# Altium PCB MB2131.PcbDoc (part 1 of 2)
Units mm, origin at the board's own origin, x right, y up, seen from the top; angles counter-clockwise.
Board outline 22 x 56 mm, 2 copper layers (Top Layer, Bottom Layer), stack 0.87 mm thick; 89 components, 71 nets, 391 pads, 308 vias.
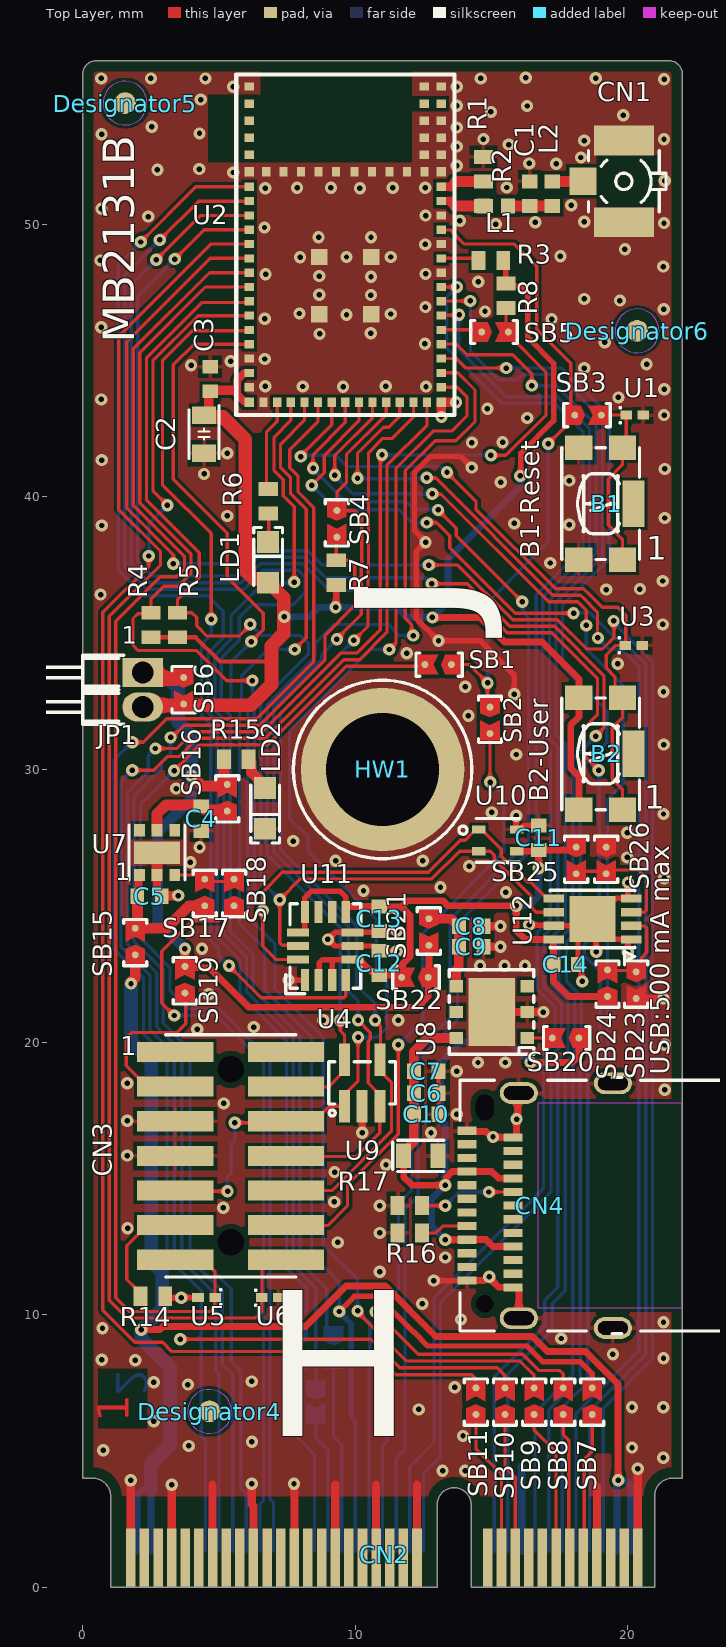
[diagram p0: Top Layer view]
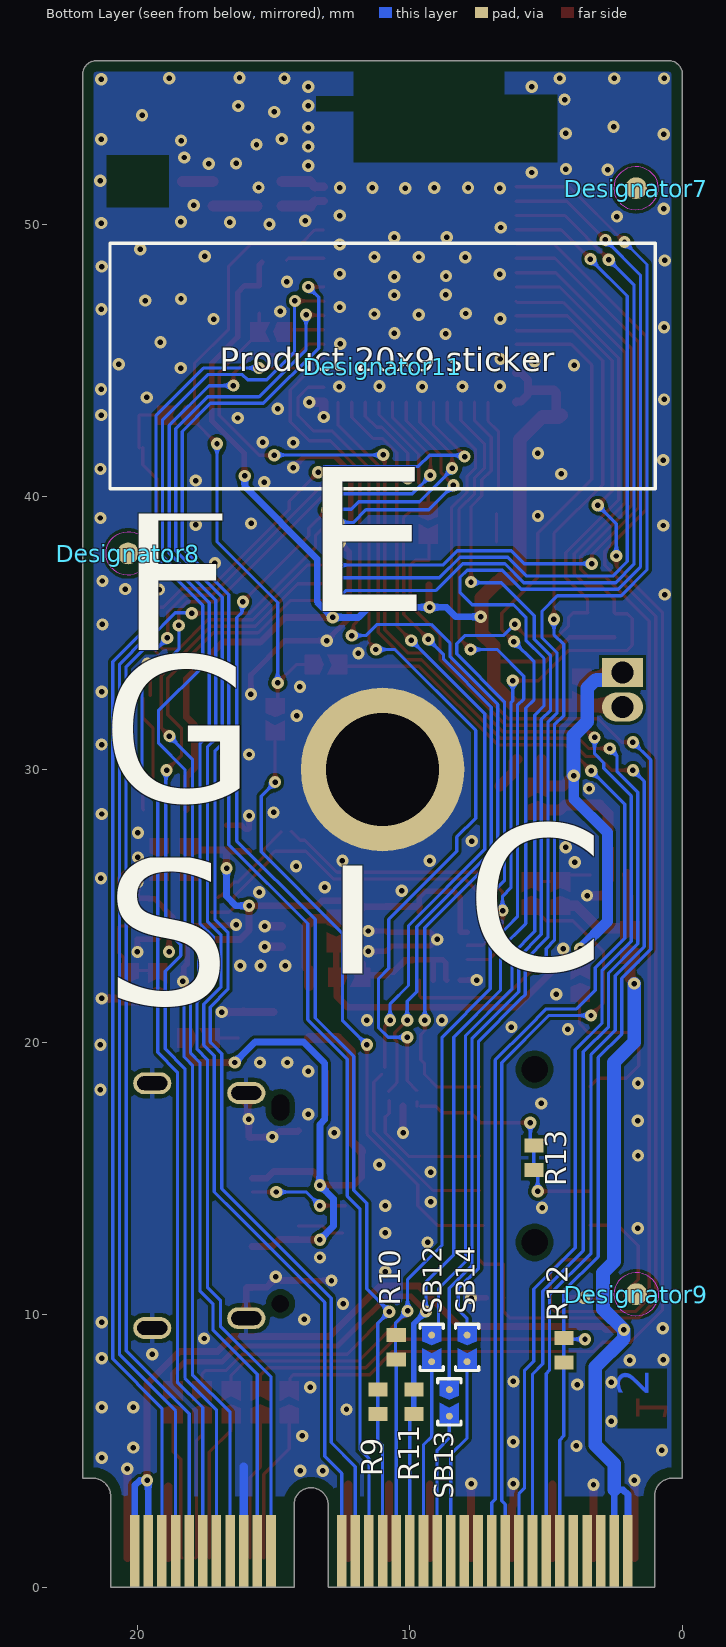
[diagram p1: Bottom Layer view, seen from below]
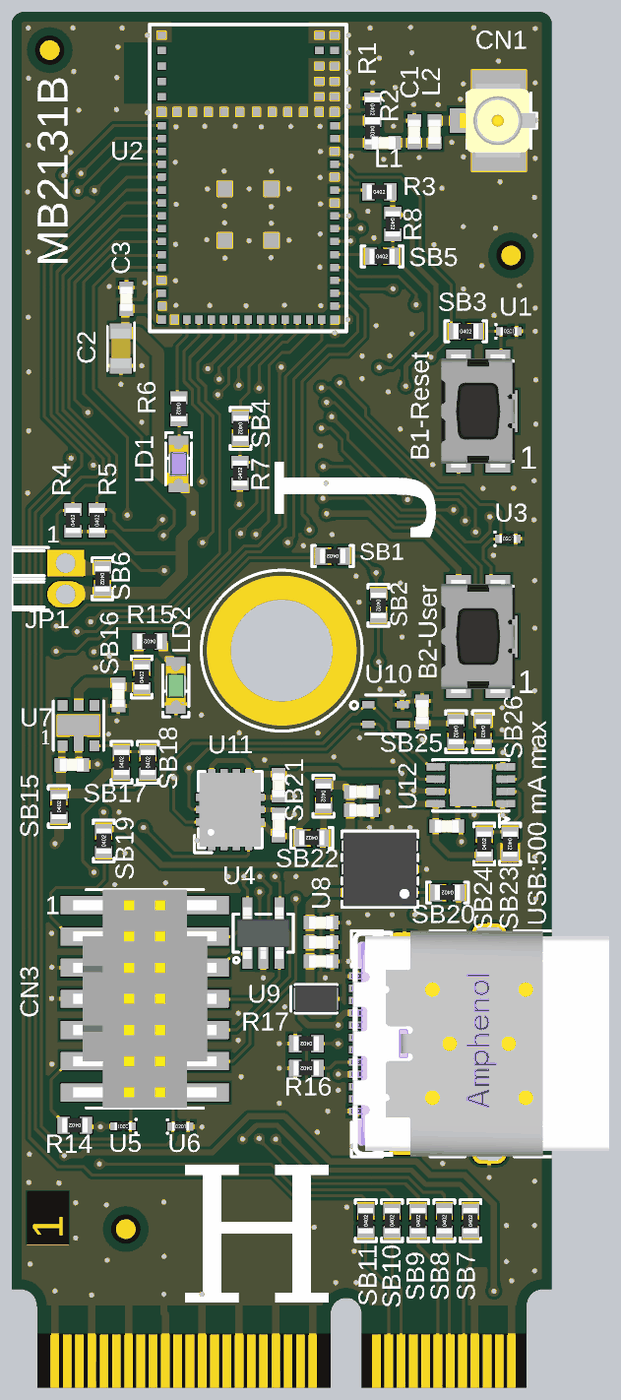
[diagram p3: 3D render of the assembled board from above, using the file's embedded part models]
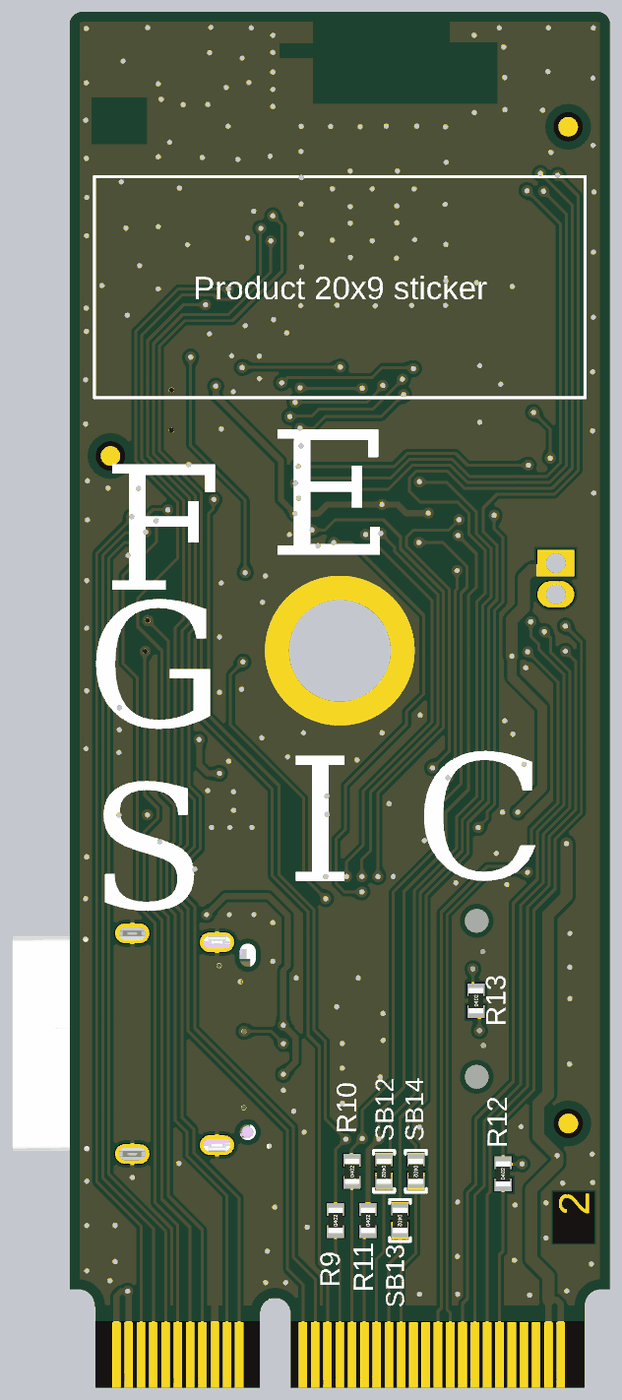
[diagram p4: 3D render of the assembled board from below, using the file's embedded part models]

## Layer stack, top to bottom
Top Solder: solder mask 0.015, Solder Resist, Dk 3.5
Top Layer: signal copper 0.035
Dielectric 1: core 0.8, FR-4, Dk 4.8
Bottom Layer: signal copper 0.035
Bottom Solder: solder mask 0.015, Solder Resist, Dk 3.5

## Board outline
1.025,0 1.025,3.337 ccw(c0.362,3.337) 0.362,4 0,4 0,55.5 cw(c0.5,55.5) 0.5,56 21.5,56 cw(c21.5,55.5) 22,55.5 22,4 21.638,4 ccw(c21.638,3.337) 20.975,3.337 20.975,0 14.25,0 14.25,3.025 ccw(c13.625,3.025) 13.625,3.65 ccw(c13.625,3.025) 13,3.025 13,0

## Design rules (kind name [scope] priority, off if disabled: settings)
BoardOutlineClearance [All] p1: gap=0.4 ignorepadtopadclearanceinfootprint=FALSE
Clearance [All] p1: gap=0.12 ignorepadtopadclearanceinfootprint=TRUE except(0: THPad-Hole; 0.15: Via-Text Fill-Fill Fill-Poly Fill-Region Fill-Text Poly-Poly Poly-Region Poly-Text Region-Region Region-Text Text-Text; 0.2: Track-Hole SMDPad-SMDPad SMDPad-THPad SMDPad-Text SMDPad-Hole THPad-THPad THPad-Text Poly-Hole; 0.3: Arc-Hole Via-Hole Fill-Hole Region-Hole Text-Hole)
ComponentClearance [All] p1: gap=0.1 collisioncheckmode=3 verticalgap=0 showdistances=FALSE
HoleSize [All] p1: absolutevalues=TRUE maxlimit=10 minlimit=0.025 maxpercent=80.000 minpercent=20.000
MinimumSolderMaskSliver [All] p1: minsoldermaskwidth=0.1
PlaneConnect [All] p1: planeconnectstyle=Relief reliefexpansion=0.508 reliefentries=4 reliefconductorwidth=0.21 reliefairgap=0.21
PolygonConnect PolygonConnect_via [IsVia] p1: connectstyle=Direct reliefconductorwidth=0.254 reliefentries=4 polygonreliefangle="90 Angle" airgapwidth=0.254
PolygonConnect [All] p2: connectstyle=Relief reliefconductorwidth=0.15 reliefentries=4 polygonreliefangle="90 Angle" airgapwidth=0.15
RoutingVias [All] p1: holewidth=0.3 width=0.55 viastyle="Through Hole" minholewidth=0.3 minwidth=0.55 maxholewidth=0.3 maxwidth=0.55 useviatemplates=TRUE viatemplateguid#1={F3ABD56A-64D8-4EC3-B00D-3E2DD87A5A49} viatemplatename#1=v45h20m0mx0
SilkToSilkClearance [All] p1: silktosilkclearance=0.2
SilkToSolderMaskClearance [IsPad] p1: minsilkscreentomaskgap=0.2 clearancetoexposedcopper=TRUE
SolderMaskExpansion [All] p1: expansion=0.102 istentingtop=FALSE
Width Width_RF [InNetClass('RF')] p1: maxlimit=1.3 minlimit=0.4 preferedwidth=1.3 toplayer_maxwidth=0.4 toplayer_prefwidth=0.4 impedanceprofiledriven=TRUE impedanceprofileid={58A662D9-11D8-47AE-92A8-C80169B12F76} impedanceprofilevalue=50.000000 minimp=50.000000 maximp=50.000000 favimp=50.000000
Width Width_Alim [InNetClass('Alim')] p2: maxlimit=0.5 minlimit=0.2 preferedwidth=0.25 minimp=50.000000 maximp=50.000000 favimp=50.000000
Width [All] p3: maxlimit=0.5 minlimit=0.12 preferedwidth=0.12 minimp=50.000000 maximp=50.000000 favimp=50.000000
24 further rules are at their usual default settings.

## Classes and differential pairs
net class RF: ANT ANTIN ANTOUT NetC1_2
component class U_Mems: C11 C12 C13 C14 SB22 SB23 SB24 SB25 SB26 U10 U11 U12
component class U_MCU: B1 B2 C1 C2 C3 CN1 JP1 L1 L2 LD1 R1 R2 R3 R4 R5 R6 R7 R8 SB1 SB2 SB3 SB4 SB5 SB6 U1 U2 U3
component class U_M2: CN2 HW1 R9 R10 R11 R12 SB7 SB8 SB9 SB10 SB11 SB12 SB13 SB14
component class U_External_Debug_Interface: CN3 R13 R14 U4 U5 U6
component class U_Board_Power: C4 C5 C6 C7 C8 C9 C10 CN4 LD2 R15 R16 R17 SB15 SB16 SB17 SB18 SB19 SB20 SB21 U7 U8 U9

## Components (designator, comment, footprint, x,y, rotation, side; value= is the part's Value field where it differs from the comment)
B1 "SW-PUSH-CMS_KMR2_BLACK" SWI_C&K_Y78B23110FP__ITT_KMR231GLFS 19,39.75 r270 top value=KMR231GLFS
B2 "SW-PUSH-CMS_KMR2_BLACK" SWI_C&K_Y78B23110FP__ITT_KMR231GLFS 19,30.575 r270 top value=KMR231GLFS
C1 "Capacitor" C0402 16.4,51.125 r270 top value=22pF
C2 "Capacitor" C0603 4.45,42.3 r90 top value=4.7uF
C3 "Capacitor" C0402 4.675,44.325 r270 top value=100nF
C4 "Capacitor" C0402 4.35,28.2 r90 top value=100nF
C5 "Capacitor" C0402 2.45,25.35 r180 top value=1uF
C6 "Capacitor" C0402 12.6,18.125 r180 top value=1uF
C7 "Capacitor" C0402 12.6,18.925 r180 top value=100nF
C8 "Capacitor" C0402 14.25,24.25 r180 top value=1uF
C9 "Capacitor" C0402 14.25,23.5 r180 top value=100nF
C10 "Capacitor" C0402 12.6,17.35 r180 top value=100pF
C11 "Capacitor" C0402 16.725,27.5 r270 top value=100nF
C12 "Capacitor" C0402 10.875,22.9 r270 top value=100nF
C13 "Capacitor" C0402 10.875,24.525 r90 top value=100nF
C14 "Capacitor" C0402 17.725,22.85 r180 top value=100nF
CARTOUCH-1 "Comment" Sheetbox_2L2S -32.492,-33.227 r0 top
CN1 "U.FL-R-SMT-1" CON_HRS_U.FL-R-SMT-1 19.85,51.575 r270 top value=Con_RF_U.FL-R-SMT-1
CN2 "M2_MALE-CONNECTOR_KEY-E_3V3" CON_BOARD_GOLDFINGER_PCI_EXPRESS_X75_M2_KEY-E 11,0 r0 top value=M.2_KeyE_Male
CN3 "Header 7x2" CON_STDC14_Receiver_SMALL 5.425,15.825 r270 top
CN4 "USB_TYPE_C_Receptacle" CON_USB-TYPEC_AMPHENOL_12401826E412A 14.75,14 r90 top value=USB_C_12401826E412A
Designator4 "Comment" MIRE_PLACE_SMD_0P8MM 4.65,6.45 r0 top
Designator5 "Comment" MIRE_PLACE_SMD_0P8MM 1.552,54.446 r0 top
Designator6 "Comment" MIRE_PLACE_SMD_0P8MM 20.339,46.091 r0 top
Designator7 "Comment" MIRE_PLACE_SMD_0P8MM 1.7,51.325 r180 bottom
Designator8 "Comment" MIRE_PLACE_SMD_0P8MM 20.339,37.926 r180 bottom
Designator9 "Comment" MIRE_PLACE_SMD_0P8MM 1.692,10.751 r180 bottom
Designator11 "Comment" STICKER_PRODUCT_20X9 11,44.8 r180 bottom
HW1 "M2_POSITION_HOLE" MISC_REGO_S001_00001_A42_R 11,30 r0 top value=S001-00001-A42-R
JP1 "Jumper_Header1.27 2x1 Fitted" CON_WP_707-2-02-2-20-00 2.2,32.925 r270 top value="Header 2x1"
L1 "Inductor" C0402 15.15,50.675 r0 top value=3.3nH
L2 "Inductor" C0402 17.225,51.125 r90 top value=3.3nH
LD1 "LED_blue" LED_0603_OSRAM_LB-Q39G-L2OO-35-1_BLUE_1A2K_H0P4 6.8,37.6 r90 top value=Blue
LD2 "LED_green" LED_0603_OSRAM_LG-Q396-PS-35_GREEN_1A2K_H0P4 6.69,28.575 r270 top value=Green
R1 "Resistor" R0402 14.7,52.025 r270 top value=0R
R2 "Resistor" R0402 14.7,51.125 r270 top value=0R
R3 "Resistor" R0402 14.975,48.675 r0 top value=10K
R4 "Resistor" R0402 2.5,35.3 r90 top value=3K3
R5 "Resistor" R0402 3.475,35.3 r90 top value=3K3
R6 "Resistor" R0402 6.804,39.844 r270 top value=150R
R7 "Resistor" R0402 9.3,37.225 r90 top value=3K3
R8 "Resistor" R0402 15.525,47.375 r270 top value=3K3
R9 "Resistor" R0402 11.175,6.8 r90 bottom value=0R
R10 "Resistor" R0402 10.5,8.8 r90 bottom value=0R
R11 "Resistor" R0402 9.85,6.8 r90 bottom value=0R
R12 "Resistor" R0402 4.35,8.7 r90 bottom value=0R
R13 "Resistor" R0402 5.45,15.75 r90 bottom value=0R
R14 "Resistor" R0402 2.575,10.675 r180 top value=100R
R15 "Resistor" R0402 5.625,30.375 r180 top value=620R
R16 "Resistor" R0402 12,13 r180 top value=5K1
R17 "Resistor" R0402 12,14 r180 top value=5K1
SB1 "SB_ON" SOLDER-BRIDGE_R0402-0R 13.075,33.85 r180 top value=0R
SB2 "SB_ON" SOLDER-BRIDGE_R0402-0R 14.94,31.84 r270 top value=0R
SB3 "SB_ON" SOLDER-BRIDGE_R0402-0R 18.5,43 r0 top value=0R
SB4 "SB_ON" SOLDER-BRIDGE_R0402-0R 9.325,39.05 r270 top value=0R
SB5 "SB_ON" SOLDER-BRIDGE_R0402-0R 15.088,46.05 r0 top value=0R
SB6 "SB_ON" SOLDER-BRIDGE_R0402-0R 3.7,32.925 r270 top value=0R
SB7 "SB_ON" SOLDER-BRIDGE_R0402-0R 18.69,6.789 r90 top value=0R
SB8 "SB_ON" SOLDER-BRIDGE_R0402-0R 17.624,6.789 r90 top value=0R
SB9 "SB_ON" SOLDER-BRIDGE_R0402-0R 16.558,6.789 r90 top value=0R
SB10 "SB_ON" SOLDER-BRIDGE_R0402-0R 15.491,6.789 r90 top value=0R
SB11 "SB_ON" SOLDER-BRIDGE_R0402-0R 14.425,6.789 r90 top value=0R
SB12 "SB_ON" SOLDER-BRIDGE_R0402-0R 9.2,8.8 r270 bottom value=0R
SB13 "SB_ON" SOLDER-BRIDGE_R0402-0R 8.55,6.8 r270 bottom value=0R
SB14 "SB_ON" SOLDER-BRIDGE_R0402-0R 7.9,8.8 r270 bottom value=0R
SB15 "SB_ON" SOLDER-BRIDGE_R0402-0R 1.925,23.65 r90 top value=0R
SB16 "SB_ON" SOLDER-BRIDGE_R0402-0R 5.3,28.925 r90 top value=0R
SB17 "SB_ON" SOLDER-BRIDGE_R0402-0R 4.475,25.45 r90 top value=0R
SB18 "SB_ON" SOLDER-BRIDGE_R0402-0R 5.55,25.45 r90 top value=0R
SB19 "SB_ON" SOLDER-BRIDGE_R0402-0R 3.75,22.25 r90 top value=0R
SB20 "SB_ON" SOLDER-BRIDGE_R0402-0R 17.75,20.15 r180 top value=0R
SB21 "SB_ON" SOLDER-BRIDGE_R0402-0R 12.7,24.075 r270 top value=0R
SB22 "SB_ON" SOLDER-BRIDGE_R0402-0R 12.225,22.375 r180 top value=0R
SB23 "SB_ON" SOLDER-BRIDGE_R0402-0R 20.3,22.125 r270 top value=0R
SB24 "SB_ON" SOLDER-BRIDGE_R0402-0R 19.25,22.125 r90 top value=0R
SB25 "SB_ON" SOLDER-BRIDGE_R0402-0R 18.1,26.7 r270 top value=0R
SB26 "SB_ON" SOLDER-BRIDGE_R0402-0R 19.2,26.7 r270 top value=0R
U1 "ESD-TRANSIL" ESD_ST0201 20.25,43 r0 top value=ESDALC6V1-1U2
U2 "STM32WBA5M" MOD_STM_76P_8X12P5_H1P37 9.633,49.247 r0 top value=STM32WBA5MMGH6
U3 "ESD-TRANSIL" ESD_ST0201 20.212,34.55 r0 top value=ESDALC6V1-1U2
U4 "ESDALC6V1W5" ESD_SOT323-5L 10.25,18.5 r0 top
U5 "ESD-TRANSIL" ESD_ST0201 4.541,10.638 r180 top value=ESDALC6V1-1U2
U6 "ESD-TRANSIL" ESD_ST0201 6.875,10.625 r0 top value=ESDALC6V1-1U2
U7 "AP22814ASN-7" ICC_DFN2020-6-EPAD_2X2_P065 2.725,26.95 r0 top
U8 "LD39050PU33R" ICC_DFN6-EPAD_3X3_P095 15,21.1 r90 top
U9 "ESD-TRANSIL" ESD_QFN1610_2N_1K_2A 12.4,15.825 r0 top value=ESDA25P35-1U1M
U10 "SHT4X" ICC_SENSOR_SHT40-AD1B-R2_DFN4-EPAD_1P5X1P5_P050 15.225,27.4 r0 top value=SHT40-AD1B-R2
U11 "ISM330DHCX" ICC_LGA14_3X2P5_P050 8.9,23.525 r90 top value=ISM330DHCXTR
U12 "M24128-DFMC6TP" ICC_DFN8-EPAD_2X3_P050 18.7,24.515 r270 top value=M24256-DFMC6TG

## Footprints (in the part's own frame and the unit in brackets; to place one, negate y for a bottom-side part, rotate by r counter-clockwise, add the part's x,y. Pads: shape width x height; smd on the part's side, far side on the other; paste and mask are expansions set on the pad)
C0402 [mm]
  rect 0.51x0.56 smd mask+0.05: 1(-0.45,0) 2(0.45,0)
  body extent -0.5,-0.3 0.5,0.3, height 0.4
C0603 [mm]
  rect 0.64x0.89 smd mask+0.05: 1(-0.7,0) 2(0.7,0)
  silkscreen extent -0.9,-0.55 1.05,0.55, body extent -0.9,-0.5 0.9,0.5, height 1.4
CON_BOARD_GOLDFINGER_PCI_EXPRESS_X75_M2_KEY-E [mm] "MCD-03876"
  rect 0.35x2.15 smd paste-1 mask+0.05: 1(9.362,1.075) 3(8.862,1.075) 5(8.362,1.075) 7(7.862,1.075) 9(7.362,1.075) 11(6.863,1.075) 13(6.363,1.075) 15(5.863,1.075) 17(5.363,1.075) 19(4.863,1.075) 21(4.363,1.075) 23(3.863,1.075) 33(1.262,1.075) 35(0.763,1.075) 37(0.263,1.075) 39(-0.237,1.075) 41(-0.737,1.075) 43(-1.237,1.075) 45(-1.737,1.075) 47(-2.237,1.075) 49(-2.737,1.075) 51(-3.237,1.075) 53(-3.737,1.075) 55(-4.237,1.075) 57(-4.738,1.075) 59(-5.238,1.075) 61(-5.738,1.075) 63(-6.238,1.075) 65(-6.738,1.075) 67(-7.238,1.075) 69(-7.738,1.075) 71(-8.238,1.075) 73(-8.738,1.075) 75(-9.237,1.075)
  rect 0.35x2.65 smd far side paste-1 mask+0.05: 2(9.094,1.325) 4(8.594,1.325) 6(8.094,1.325) 8(7.594,1.325) 10(7.094,1.325) 12(6.594,1.325) 14(6.094,1.325) 16(5.594,1.325) 18(5.094,1.325) 20(4.594,1.325) 22(4.094,1.325) 32(1.5,1.325) 34(1,1.325) 36(0.5,1.325) 38(0,1.325) 40(-0.5,1.325) 42(-1,1.325) 44(-1.5,1.325) 46(-2,1.325) 48(-2.5,1.325) 50(-3,1.325) 52(-3.5,1.325) 54(-4,1.325) 56(-4.5,1.325) 58(-5,1.325) 60(-5.5,1.325) 62(-6,1.325) 64(-6.5,1.325) 66(-7,1.325) 68(-7.5,1.325) 70(-8,1.325) 72(-8.5,1.325) 74(-9,1.325)
CON_HRS_U.FL-R-SMT-1 [mm] "MCD-01583"
  rect 1x1 smd mask+0.05: 1(0,-1.5)
  rect 1.1x2.2 smd mask+0.05: 2(-1.5,0) 3(1.5,0)
  silkscreen extent -1.12,-1.3 1.12,1.55, body extent -1.5,-1.6 1.5,1.5, height 1.25
CON_STDC14_Receiver_SMALL [mm] "compatible with Samtec FTSH-107-01-L-DV,-K,-A,-P"
  round 0 hole 0.97 unplated mask+0.05: 0(-3.175,0) 0(3.175,0)
  rect 0.74x2.79 smd mask+0.05: 1(-3.81,-2.032) 2(-3.81,2.032) 3(-2.54,-2.032) 4(-2.54,2.032) 5(-1.27,-2.032) 6(-1.27,2.032) 7(0,-2.032) 8(0,2.032) 9(1.27,-2.032) 10(1.27,2.032) 11(2.54,-2.032) 12(2.54,2.032) 13(3.81,-2.032) 14(3.81,2.032)
  silkscreen extent -4.45,-2.39 4.45,2.39, body extent -4.45,-2.92 4.45,2.92, height 6.6
CON_USB-TYPEC_AMPHENOL_12401826E412A [mm] "MCD-03232"
  round 0 hole 0.65 unplated mask+0.05: 0(-3.6,0)
  round 0 hole 0.65 slot 0.95 at 0 deg unplated mask+0.05: 0(3.6,0)
  rect 0.3x0.7 smd mask+0.05: A1(-2.75,0.66) A2(-2.25,0.66) A3(-1.75,0.66) A4(-1.25,0.66) A5(-0.75,0.66) A6(-0.25,0.66) A7(0.25,0.66) A8(0.75,0.66) A9(1.25,0.66) A10(1.75,0.66) A11(2.25,0.66) A12(2.75,0.66) B1(2.5,-1.04) B2(2,-1.04) B3(1.5,-1.04) B4(1,-1.04) B5(0.5,-1.04) B6(0,-1.04) B7(-0.5,-1.04) B8(-1,-1.04) B9(-1.5,-1.04) B10(-2,-1.04) B11(-2.5,-1.04) B12(-3,-1.04)
  oval 0.8x1.4 hole 0.5 slot 1.1 at 90 deg mask+0.05: SH1(-4.13,-1.25) SH2(4.13,-1.25) SH3(-4.49,-4.7) SH4(4.49,-4.7)
  Top Layer keep-out region: -3.75,-7.24 3.75,-7.24 3.75,-1.95 -3.75,-1.95
  silkscreen extent -4.7,-9.59 4.7,0.91, body extent -4.6,-9.59 4.6,0.91, height 3.26
CON_WP_707-2-02-2-20-00 [mm]
  rect 1.07x1.5 hole 0.8 mask+0.05: 1(-0.635,0)
  oval 1.07x1.5 hole 0.8 mask+0.05: 2(0.635,0)
  silkscreen extent -1.27,-5.25 1.27,-0.7, body extent -1.27,-5.25 1.27,0.2, height 2.1
ESD_QFN1610_2N_1K_2A [mm] "DFN, 2-Leads, Body 1.60x1.00mm"
  rect 0.55x0.9 smd mask+0.05: 1(-0.625,0) 2(0.625,0)
  silkscreen extent -1.02,-0.58 0.85,0.58, body extent -0.85,-0.55 0.85,0.55, height 0.6
ESD_SOT323-5L [mm]
  rect 0.4x1.2 smd mask+0.05: 1(-0.65,-0.85) 2(0,-0.85) 3(0.65,-0.85) 4(0.65,0.85) 5(-0.65,0.85)
  silkscreen extent -1.22,-1.21 1.22,0.77, body extent -1.15,-1.05 1.15,1.05, height 1.1
ESD_ST0201 [mm]
  rect 0.425x0.33 smd mask+0.05: 1(-0.312,0) 2(0.312,0)
  silkscreen extent -0.55,-0.3 -0.5,0.3, body extent -0.34,-0.18 0.34,0.18, height 0.34
ICC_DFN6-EPAD_3X3_P095 [mm]
  rect 0.45x0.5 smd mask+0.05: 1(-0.95,-1.3) 2(0,-1.3) 3(0.95,-1.3) 4(0.95,1.3) 5(0,1.3) 6(-0.95,1.3)
  rect 2.5x1.7 smd mask+0.05: EP(0,0)
  silkscreen extent -1.55,-1.55 1.55,1.55, body extent -1.55,-1.55 1.55,1.55, height 1
ICC_DFN8-EPAD_2X3_P050 [mm]
  rect 0.3x0.75 smd mask+0.05: 1(0.75,1.425) 2(0.25,1.425) 3(-0.25,1.425) 4(-0.75,1.425) 5(-0.75,-1.425) 6(-0.25,-1.425) 7(0.25,-1.425) 8(0.75,-1.425)
  rect 1.7x1.7 smd mask+0.05: EP(0,0)
  silkscreen extent -1.05,-1.55 1.55,1.55, body extent -1.05,-1.55 1.05,1.55, height 0.9
ICC_DFN2020-6-EPAD_2X2_P065 [mm] "MCD-012963"
  rect 0.4x0.45 smd mask+0.05: 1(-0.65,-0.825) 2(0,-0.825) 3(0.65,-0.825) 4(0.65,0.825) 5(0,0.825) 6(-0.65,0.825)
  rect 1.7x0.825 smd mask+0.05: 7(0,0)
  Top Layer region: -0.2,0.2 0.2,0.2 0.2,-1.05 -0.2,-1.05
  silkscreen extent -1.02,-1 1.02,1, body extent -1,-1 1,1, height 1.01
ICC_LGA14_3X2P5_P050 [mm] "MCD-01387"
  rect 0.8x0.3 smd mask+0.05: 1(-1.25,0.75) 2(-1.25,0.25) 3(-1.25,-0.25) 4(-1.25,-0.75) 8(1.25,-0.75) 9(1.25,-0.25) 10(1.25,0.25) 11(1.25,0.75)
  rect 0.3x0.8 smd mask+0.05: 5(-0.5,-1) 6(0,-1) 7(0.5,-1) 12(0.5,1) 13(0,1) 14(-0.5,1)
  silkscreen extent -1.75,-1.3 1.55,1.45, body extent -1.55,-1.3 1.55,1.3, height 0.86
ICC_SENSOR_SHT40-AD1B-R2_DFN4-EPAD_1P5X1P5_P050 [mm] "MCD-03381"
  rect 0.5x0.3 smd mask+0.05: 1(-0.7,0.4) 2(-0.7,-0.4) 3(0.7,-0.4) 4(0.7,0.4)
  silkscreen extent -0.8,-0.8 0.8,0.8, body extent -0.8,-0.8 0.8,0.8, height 0.61
LED_0603_OSRAM_LB-Q39G-L2OO-35-1_BLUE_1A2K_H0P4 [mm]
  rect 0.8x0.8 smd mask+0.05: 1(-0.75,0) 2(0.75,0)
  silkscreen extent -0.85,-0.53 1.28,0.53, body extent -0.85,-0.45 0.85,0.45, height 0.6
LED_0603_OSRAM_LG-Q396-PS-35_GREEN_1A2K_H0P4 [mm]
  rect 0.8x0.8 smd mask+0.05: 1(-0.75,0) 2(0.75,0)
  silkscreen extent -0.85,-0.53 1.28,0.53, body extent -0.85,-0.45 0.85,0.45, height 0.6
MIRE_PLACE_SMD_0P8MM [mm]
  round 0.8 smd paste-10 mask+0.2: 1(0,0)
  Top Layer keep-out circle w0.01: c0,0 r0.804
MISC_REGO_S001_00001_A42_R [mm] "MCD-03863"
  round 6 hole 4.15 mask+0.05: 1(0,0)
  silkscreen extent -3.27,-3.27 3.27,3.27, body extent -2.8,-2.8 2.8,2.8, height 2.5
MOD_STM_76P_8X12P5_H1P37 [mm] "MCD-03538"
  rect 0.35x0.3 smd mask+0.04: 1(-3.525,5.803) 2(-3.525,5.178) 3(-3.525,4.553) 4(-3.525,3.928) 5(-3.525,3.303) 7(-3.525,2.128) 8(-3.525,1.603) 9(-3.525,1.078) 10(-3.525,0.555) 11(-3.525,0.028) 12(-3.525,-0.497) 13(-3.525,-1.022) 14(-3.525,-1.547) 15(-3.525,-2.072) 16(-3.525,-2.597) 17(-3.525,-3.122) 18(-3.525,-3.647) 19(-3.525,-4.172) 20(-3.525,-4.697) 21(-3.525,-5.222) 37(3.525,-5.222) 38(3.525,-4.697) 39(3.525,-4.172) 40(3.525,-3.647) 41(3.525,-3.122) 42(3.525,-2.597) 43(3.525,-2.072) 44(3.525,-1.547) 45(3.525,-1.022) 46(3.525,-0.497) 47(3.525,0.028) 48(3.525,0.555) 49(3.525,1.078) 50(3.525,1.603) 51(3.525,2.128) 53(3.525,3.303) 54(3.525,3.928) 55(3.525,4.553) 56(3.525,5.178) 57(3.525,5.803) 58(2.9,5.803) 59(2.9,5.178) 60(2.9,4.553) 61(2.9,3.928) 62(2.9,3.303)
  rect 0.35x0.35 smd mask+0.04: 6(-3.525,2.678) 22(-3.525,-5.772) 36(3.525,-5.772) 52(3.525,2.678)
  rect 0.3x0.35 smd mask+0.04: 23(-3,-5.772) 24(-2.5,-5.772) 25(-2,-5.772) 26(-1.5,-5.772) 27(-1,-5.772) 28(-0.5,-5.772) 29(0,-5.772) 30(0.5,-5.772) 31(1,-5.772) 32(1.5,-5.772) 33(2,-5.772) 34(2.5,-5.772) 35(3,-5.772) 63(2.9,2.678) 64(2.258,2.678) 65(1.618,2.678) 66(0.978,2.678) 67(0.338,2.678) 68(-0.342,2.678) 69(-0.982,2.678) 70(-1.622,2.678) 71(-2.262,2.678) 72(-2.9,2.678)
  rect 0.6x0.6 smd mask+0.04: 73(-0.95,-0.447) 74(-0.95,-2.547) 75(0.95,-2.547) 76(0.95,-0.447)
  silkscreen extent -4,-6.25 4,6.25, body extent -4,-6.25 4,6.24, height 1.41
R0402 [mm]
  rect 0.51x0.7 smd mask+0.05: 1(-0.45,0) 2(0.45,0)
  body extent -0.52,-0.3 0.52,0.3, height 0.4
Sheetbox_2L2S [mil] "Sheetbox 2 layers / 2 silkscreens"
  round 20 on Mech16: 1(813.78,210.69) 1(2736.9,210.69)
SOLDER-BRIDGE_R0402-0R [mil] "MCD-01619"
  round 10 smd paste-393.7: 1(-17.72,0) 2(20.67,0)
  Top Layer region: -30.51,-13.78 -30.51,13.78 -8.86,13.78 -2.95,0 -8.86,-13.78
  Top Layer region: 1.48,13.78 8.37,0 1.48,-13.78 30.51,-13.78 30.51,13.78
  silkscreen extent -33,-17 33,17, body extent -20,-12 20,12, height 14
STICKER_PRODUCT_20X9 [mm]
  silkscreen extent -10,-4.5 10,4.5
SWI_C&K_Y78B23110FP__ITT_KMR231GLFS [mm] "MCD-00715"
  rect 0.9x1 smd mask+0.05: 1(2.05,0.8) 2(2.05,-0.8) 3(-2.05,0.8) 4(-2.05,-0.8)
  rect 1.7x0.8 smd mask+0.05: 5(0,1.2)
  silkscreen extent -2.05,-1.43 2.05,1.43, body extent -2.3,-1.5 2.3,1.5, height 2.1

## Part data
B1 B2: library part MCD-01485, "Switch tactile, SPST-NO, 32V, 50mA, 2.8x4.6mm", Manufacturer=C&K, Manufacturer_HQ_COO=Unknown, Manufacturer_Part_Number=KMR231GLFS, Package=2.8x4.6mm
C1: library part MCD-01995, "Capacitor, MLCC, 22pF, 50V, C0G, +/-5%, 0402, T=0.5mm", Manufacturer=TDK, Manufacturer_Part_Number=C1005NP01H220J050BA, Package=0402
C2: library part MCD-00009, "Capacitor, MLCC, 4.7uF, 16V, X5R, +/-10%, 0603, T=0.8mm", Manufacturer=YAGEO, Manufacturer_Part_Number=CC0603KRX5R7BB475, Package=0603
C3 C4 C7 C9 C11 C12 C13 C14: library part MCD-00006, "Capacitor, MLCC, 100nF, 16V, X7R, +/-10%, 0402, T=0.5mm", Manufacturer=YAGEO, Manufacturer_Part_Number=CC0402KRX7R7BB104, Package=0402
C5 C6 C8: library part MCD-00095, "Capacitor, MLCC, 1uF, 25V, X5R, +/-10%, 0402, T=0.5mm", Manufacturer=MURATA, Manufacturer_Part_Number=GRM155R61E105KA12, Package=0402
C10: library part MCD-00205, "Capacitor, MLCC, 100pF, 50V, NPO, +/-5%, 0402, T=0.5mm", Manufacturer=YAGEO, Manufacturer_Part_Number=CC0402JRNPO9BN101, Package=0402
CN1: library part MCD-01583, "Connector_RF, 0Hz to 6GHz, 50R, VR, SMD, T= 1.25mm", Manufacturer=HIROSE
CN2: library part MCD-03876, "M.2 Male connector (NGFF), 67pins, keyE", Manufacturer=N/A, Package="M.2 Key E"
CN3: library part MCD-00639, "Header, 7x2, 1.27mm, VR, SMD, T=5.97mm", Manufacturer=SAMTEC, Manufacturer_Part_Number=FTSH-107-01-L-DV-K
CN4: library part MCD-03232, "USB_TypeC, 24 pins, RA, SMD, T=2.96mm", Manufacturer="AMPHENOL ICC", Manufacturer_Part_Number=12401826E412A
HW1: library part MCD-03863, "NGFF Standoff, Brass, For M2 connector 4.2mm, diameter 5.5 / 4 and screw M3x3.7", Manufacturer="REGO ELECTRONICS INC", Manufacturer_Part_Number=S001-00001-A42-R
JP1: library part MCD-01428, "Header, 2x1, 1.27mm, RA, TH, T=3.05mm/1.27mm", Manufacturer="W&P PRODUCTS", Manufacturer_Part_Number=707-2-02-2-20-00
L1 L2: library part MCD-03001, "Inductor, 3.3nH, +/-0.3nH, 0.8A,125mR, 0402, T=0.5mm", Manufacturer=MURATA, Manufacturer_Part_Number=LQG15HS3N3S02, Package=0402
LD1: library part MCD-00585, "LED, Blue, 2V85, 5mA, 0603", Manufacturer="OSRAM OPTO SEMICONDUCTORS", Manufacturer_Part_Number="LB Q39G-L2OO-35-1", Package=0603
LD2: library part MCD-00588, "LED, Green, 2V, 20mA, 0603", Manufacturer="OSRAM OPTO SEMICONDUCTORS", Manufacturer_Part_Number="LG Q396-PS-35", Package=0603
R1 R2 R9 R10 R11 R12 R13: library part MCD-00052, "Resistor, 0R, 0402, +/-5%, 1/16W", Manufacturer=YAGEO, Manufacturer_Part_Number=RC0402JR-070RL, Package=0402
R3: library part MCD-00053, "Resistor, 10K, 0402, +/-1%, 1/16W", Manufacturer=YAGEO, Manufacturer_Part_Number=RC0402FR-0710KL, Package=0402
R4 R5 R7 R8: library part MCD-00184, "Resistor, 3K3, 0402, +/-1%, 1/16W", Manufacturer=YAGEO, Manufacturer_Part_Number=RC0402FR-073K3L, Package=0402
R6: library part MCD-00393, "Resistor, 150R, 0402, +/-1%, 1/16W", Manufacturer=YAGEO, Manufacturer_Part_Number=RC0402FR-07150RL, Package=0402
R14: library part MCD-00067, "Resistor, 100R, 0402, +/- 1%, 1/16W", Manufacturer=YAGEO, Manufacturer_Part_Number=RC0402FR-07100RL, Package=0402
R15: library part MCD-00499, "Resistor, 620R, 0402, +/-1%, 1/16W", Manufacturer=YAGEO, Manufacturer_Part_Number=RC0402FR-07620RL, Package=0402
R16 R17: library part MCD-00333, "Resistor, 5K1, 0402, +/-1%, 1/16W", Manufacturer=YAGEO, Manufacturer_Part_Number=RC0402FR-075K1L, Package=0402
SB1 SB2 SB3 SB4 SB5 SB6 SB7 SB8 SB9 SB10 SB11 SB12 SB13 SB14 SB15 SB16 SB17 SB18 SB19 SB20 SB21 SB22 SB23 SB24 SB25 SB26: library part MCD-01618, "Resistor, 0R, SB0402, 5%, 0.063W", Manufacturer=YAGEO, Manufacturer_Part_Number=RC0402JR-070RL, Package=0402
U1 U3 U5 U6: library part MCD-00170, "Diode, ESD TVS, 3V, 100nA, 8V, ST0201", Manufacturer=STMICROELECTRONICS, Manufacturer_HQ_COO=EU, Manufacturer_Part_Number=ESDALC6V1-1U2, Package=ST0201
U2: library part MCD-03538, "STM32 Module with RF  integer", Manufacturer=STMICROELECTRONICS, Manufacturer_Part_Number=STM32WBA5MMGH6, Package=CSP
U4: library part MCD-00136, "Diode, ESD Transil, 3V, 1uA, 7V2, SOT323-5", Manufacturer=STMICROELECTRONICS, Manufacturer_HQ_COO=EU, Package=SOT323-5
U7: library part MCD-02963, "IC, Power Switch, 2V7 to 5V5, 3A", Manufacturer="DIODES INCORPORATED", Package=U-DFN2020-6
U8: library part MCD-00215, "LDO, 500mA, Low quiescent current and low noise voltage regulator", Manufacturer=STMICROELECTRONICS, Manufacturer_HQ_COO=NEC, Package=DFN-6
U9: library part MCD-01207, "Diode, ESD TVS, 22V, 200nA, 25V8, QFN1610", Manufacturer=STMICROELECTRONICS, Manufacturer_HQ_COO=EU, Manufacturer_Part_Number=ESDA25P35-1U1M, Package=QFN1610
U10: library part MCD-03381, "Sensor, High-Accuracy, Ultra-Low-Power, 16-bit  Relative Humidity and Temperature", Manufacturer=SENSIRION, Manufacturer_Part_Number=SHT40-AD1B-R2, Package=DFN
U11: library part MCD-02160, "MEMS, iNEMO inertial module with embedded Machine Learning Core: always-on 3D accelerometer and 3D gyroscope with digital output for industrial applications", Manufacturer=STMICROELECTRONICS, Manufacturer_HQ_COO=EU, Manufacturer_Part_Number=ISM330DHCXTR, Package=LGA-14
U12: library part MCD-01871, "Memory, EEPROM, 1V7 to 5V5, 256Kbit, 1MHz, DFN-8", Manufacturer=STMICROELECTRONICS, Manufacturer_HQ_COO=EU, Manufacturer_Part_Number=M24256-DFMC6TG, Package=DFN-8

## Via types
v1: diameter 0.45, hole 0.2, Top Layer to Bottom Layer, tented both sides, 308 vias

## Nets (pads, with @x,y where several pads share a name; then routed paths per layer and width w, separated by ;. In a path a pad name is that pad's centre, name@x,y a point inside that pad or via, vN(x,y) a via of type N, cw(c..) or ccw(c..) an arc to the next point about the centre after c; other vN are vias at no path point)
3V3: JP1.1 R15.2 SB6.1 SB16.2 SB19.2 SB21.2 SB22.1 | length 28.5
  Top Layer w0.25: SB19.2@3.75,22.725 4.65,22.725 6.1,21.275 12.275,21.275 12.675,21.675 SB22.1@12.675,22.375 ; 12.45,22.325 12.7,22.575 SB21.2@12.7,23.55
  Top Layer w0.35: SB19.2@3.75,22.775 v1(3.75,23.425)
  Top Layer w0.4: v1(3.986,29.774) 4,29.774 4.374,29.4 5.175,29.4 R15.2@5.175,30.375
  Top Layer w0.5: JP1.1@2.2,33.56 2.435,33.325 SB6.1@3.75,33.325
  Bottom Layer w0.4: v1(3.75,23.425) 2.75,24.425 2.75,27.683 3.986,28.919 v1(3.986,29.774)
  Bottom Layer w0.5: JP1.1@2.212,33.548 2.485,33.275 3.204,33.275 3.497,32.982 3.497,31.745 3.996,31.246 3.996,29.784 v1(3.986,29.774)
3V3_MEMs: C11.2 C12.2 C13.2 C14.2 SB22.2 SB24.1 SB25.1 U10.3 U11.2 U11.3 U11.5 U11.8 U11.11 U11.12 U12.8 | length 28.5
  Top Layer w0.2: U11.12@7.9,24.025 8.125,24.025 8.15,24.05 U11.11@8.15,24.775 8.15,25.3 8.375,25.525 9.45,25.525 9.65,25.325 9.65,24.975 U11.8@9.65,24.775 ; U11.2@8.65,22.275 8.675,22.3 8.675,22.904 8.796,23.025 9.154,23.025 ; U11.3@9.15,22.275 9.15,23.021 9.154,23.025 ; U11.5@9.9,23.025 9.154,23.025
  Top Layer w0.25: U11.8@9.65,24.975 C13.2@10.875,24.975 10.888,24.962 11.688,24.962 ; U11.5@9.903,23.022 9.925,23 10.175,23 10.595,22.58 10.745,22.58 C12.2@10.875,22.45 11.475,22.45 ; 11.525,22.45 11.625,22.55 ; SB22.2@11.725,22.45 11.725,22.86 12,23.135 12,24.65 11.688,24.962 ; U10.3@15.925,27 C11.2@16.725,27 ; v1(16.725,26.375) C11.2@16.725,27.05 18,27.05 SB25.1@18.05,27.1 ; SB24.1@19.25,21.675 17.825,21.675 17.275,22.225 U12.8@17.275,23.765 16.235,23.765 15.9,24.1 v1(15.9,25) 13.4,25 13.213,25.187 11.913,25.187 11.688,24.962
  Bottom Layer w0.25: v1(15.9,25) 16.375,25 16.725,25.35 v1(16.725,26.375)
5V: C6.2 C7.2 C10.2 CN4.A4 CN4.A9 CN4.B4 CN4.B9 SB20.1 U8.6 U9.1 | length 26.9
  Top Layer w0.25: U9.1@11.775,15.825 11.775,15.05 12.075,14.75 v1(13.3,14.75) 13.338,14.788 13.338,15.038 13.55,15.25 CN4.A9@14.09,15.25 15.001,15.25 15.244,15.007 CN4.B4@15.783,15.007 ; v1(13.3,12.75) 14.085,12.75 14.091,12.755 14.797,12.755 15.053,12.5 CN4.B9@15.79,12.5 ; v1(16.425,19.25) 17.95,19.25 18.2,19.5 SB20.1@18.2,20.15
  Top Layer w0.35: U9.1@11.775,15.975 11.775,16 11.875,16.1 11.9,16.1 12.15,16.35 C10.2@12.15,17.35 ; C6.2@12.15,18.125 C7.2@12.15,18.875 ; C7.2@12.15,18.925 12.15,19.65 12.65,20.15 U8.6@13.7,20.15 ; C10.2@12.153,17.353 12.15,17.355 12.15,18.12 C6.2@12.153,18.122
  Bottom Layer w0.25: v1@13.299,12.75 12.8,13.249 12.8,14.25 v1(13.3,14.75) 13.3,16.98 13.125,17.155 13.125,19.225 13.9,20 15.675,20 v1(16.425,19.25)
ANT: CN1.1 L2.2 | length 1.1
  Top Layer w0.4: L2.2@17.225,51.575 CN1.1@18.35,51.575
ANTIN: R1.2 R2.1 U2.51 | length 1.6
  Top Layer w0.3: U2.51@13.158,51.375 13.485,51.375
  Top Layer w0.35: 13.485,51.375 13.651,51.541
  Top Layer w0.4: 13.651,51.541 13.682,51.572 R1.2@14.697,51.572
ANTOUT: L1.1 R2.2 U2.50 | length 1.6
  Top Layer w0.3: U2.50@13.158,50.85 13.475,50.85
  Top Layer w0.35: 13.475,50.85 13.642,50.682
  Top Layer w0.4: 13.642,50.682 13.646,50.678 L1.1@14.697,50.678
BOOT0: R3.1 U2.46 | length 1.4
  Top Layer w0.12: U2.46@13.158,48.75 14.45,48.75 R3.1@14.525,48.675
CEB_REG_ON: CN2.56 SB18.1 | length 28.5
  Top Layer w0.12: v1(3.355,20.975) 2.9,21.43 2.9,23.325 4.025,24.45 5,24.45 SB18.1@5.55,25 ; SB18.1@5.475,25.05 5.475,25.086 5.562,25.173 5.562,25.201 5.596,25.201 5.645,25.25 5.675,25.25 5.675,25.025 SB18.1@5.6,24.95
  Bottom Layer w0.12: v1(3.355,20.975) 4.9,20.975 6.631,19.244 6.631,3.169 6.5,3.037 CN2.56@6.5,1.325
GND: B1.2 B1.4 C1.1 C2.1 C3.1 C4.1 C5.1 C6.1 C7.1 C8.1 C9.1 C10.1 C11.1 C12.1 C13.1 C14.1 CN1.2 CN1.3 CN2.1 CN2.7 CN2.18 CN2.33 CN2.39 CN2.45 CN2.51 CN2.57 CN2.63 CN2.69 CN2.75 CN3.5 CN3.7 CN4.A1 CN4.A12 CN4.B1 CN4.B12 CN4.SH1 CN4.SH2 CN4.SH3 CN4.SH4 HW1.1 LD2.2 R1.1 R14.1 R16.2 R17.2 SB23.2 SB26.1 U1.2 U2.1 U2.6 U2.19 U2.21 U2.23 U2.36 U2.45 U2.47 U2.49 U2.52 U2.53 U2.54 U2.55 U2.57 U2.58 U2.60 U2.61 U2.62 U2.63 U2.64 U2.65 U2.66 U2.67 U2.68 U2.69 U2.70 U2.71 U2.72 U2.73 U2.74 U2.75 U2.76 U3.2 U4.2 U5.2 U6.2 U7.2 U7.7 U8.2 U8.EP U9.2 U10.4 U11.1 U11.6 U11.7 U12.1 U12.4 U12.7 U12.EP | length 80.9
  Top Layer w0.15: C10.1@13.05,17.35 C6.1@13.05,18.125 C7.1@13.05,18.925
  Top Layer w0.2: R14.1@3.025,10.675 3.082,10.618 v1(3.616,10.618) 3.626,10.628 4.219,10.628 U5.2@4.229,10.638 ; U6.2@7.188,10.625 7.196,10.616 7.745,10.616 v1(7.754,10.607) v1@7.822,10.607 ; v1(7.55,22.275) U11.1@8.15,22.275 ; v1(8.995,23.767) 9.011,23.767 9.253,23.525 U11.6@9.9,23.525 10.675,23.525 10.85,23.35 C12.1@10.875,23.35 10.899,23.326 11.52,23.326 v1(11.52,23.335) ; v1@9.011,23.779 9.256,24.023 10.823,24.023 C13.1@10.875,24.075 v1(11.525,24.075) ; v1(12.875,11.25) CN4.A1@14.09,11.25 ; v1(14.275,41.075) 13.868,41.482 12.745,41.482 12.171,40.908 12.171,38.766 12.576,38.362 v1(12.576,38.335) 12.23,37.99 12.23,35.545 v1(13.05,34.725) 14.575,34.725 15.829,33.471 v1(15.829,32.755) ; v1(15.9,28.3) 15.9,27.825 U10.4@15.925,27.8 ; U10.4@16.025,27.8 16.175,27.95 C11.1@16.725,27.95 ; v1(16.375,24.3) 16.383,24.292 17.248,24.292 U12.7@17.275,24.265 17.284,24.274 U12.EP@18.384,24.274 ; C14.1@18.168,22.857 18.168,24.058 U12.EP@18.384,24.274 ; C14.1@18.187,22.857 18.3,22.745 18.3,22.25 v1(18.325,22.225) ; U12.EP@18.7,24.515 U12.EP@18.613,24.427 ; v1@18.832,23.315 18.832,24.195 U12.EP@18.839,24.201 ; v1@18.833,23.315 v1(18.835,23.314) ; v1(19.995,23.306) 19.997,23.306 19.997,23.774 19.266,23.774 U12.EP@18.839,24.201 ; v1(20,25.85) 20,25.315 U12.4@20.041,25.274 ; U12.EP@18.384,24.274 18.459,24.274 U12.EP@18.613,24.427 ; U12.EP@18.613,24.427 U12.EP@18.839,24.201 ; U12.EP@18.839,24.201 18.839,24.451 18.7,24.59 19.375,25.265 19.559,25.265 19.567,25.274 U12.4@20.041,25.274 ; U12.4@20.041,25.274 20.05,25.265 U12.4@20.125,25.265 20.116,25.274 U12.4@20.041,25.274
  Top Layer w0.25: v1(10.25,16.675) U4.2@10.25,17.65 ; CN4.A1@14.09,11.25 14.721,11.25 14.861,11.39 v1(14.915,11.39) ; CN4.A12@14.09,16.75 14.115,16.725 14.792,16.725 14.997,16.52 v1(15.051,16.52) 15.061,16.51 15.78,16.51 CN4.B1@15.79,16.5 15.886,16.5 15.911,16.525 v1@15.911,17.171 ; v1@14.901,11.3 14.969,11.3 15.264,11.005 15.785,11.005 CN4.B12@15.79,11 15.975,11 16,10.975 CN4.SH1@16,9.87 ; v1@15.892,17.152 v1@15.911,17.171 ; CN4.SH2@16,18.13 15.953,18.083 15.953,17.213 v1(15.915,17.175) v1@15.911,17.171
  Top Layer w0.3: CN2.75@1.763,1.075 v1(1.762,3.928) ; U7.2@2.725,26.125 2.725,25.55 2.9,25.375 C5.1@2.9,25.35 ; CN2.69@3.262,1.075 v1(3.262,3.762) ; CN2.63@4.762,1.075 4.762,3.762 ; v1(6.201,3.8) 6.201,3.037 6.262,2.975 CN2.57@6.262,1.075 ; CN2.51@7.763,1.075 v1@7.763,3.762 ; CN2.45@9.263,1.075 9.263,3.762 ; CN2.39@10.763,1.075 10.763,3.762 ; CN2.33@12.263,1.075 12.263,3.762 ; C9.1@14.7,23.5 v1(15.325,23.5) ; C8.1@14.7,24.25 v1(15.325,24.25) ; U8.EP@15,21.1 U8.2@16.075,21.1 ; U8.2@16.1,21.125 U8.2@16.075,21.1 ; U8.2@16.275,21.1 U8.2@16.075,21.1 ; U8.2@16.3,21.1 v1(16.9,21.1) ; CN2.7@18.862,1.075 18.862,3.7 ; SB23.2@20.3,21.6 21.3,21.6 v1(21.305,21.6) ; CN2.1@20.362,1.075 v1(20.362,4.347)
  Top Layer w0.35: C5.1@2.953,25.376 2.967,25.362 3.488,25.362 v1(3.5,25.375) ; v1@13.158,42.933 U2.36@13.158,43.475 v1(13.695,43.475)
  Bottom Layer w0.3: CN2.18@16.094,1.325 16.094,4.419 16.1,4.425
  other v1: 7.75,3.8 13.2,4.274 14.025,4.275 21.3,4.75 0.751,5.029 20.15,5.125 3.89,5.184 6.207,5.334 13.95,5.55 2.605,6.087 12.325,6.525 20.15,6.6 21.3,6.6 13.65,7.341 3.86,7.436 2.605,7.525 6.201,7.55 1.929,8.323 0.698,8.35 21.305,8.4 19.45,8.55 17.55,9.125 0.725,9.5 21.305,9.718 13.875,9.825 12.45,10.4 10.9,11.575 13.3,12.1 9.35,12.65 10.9,13 1.644,13.167 5.15,13.924 10.9,14 9.23,14.137 9.239,15.23 11.125,15.5 1.631,15.837 12.775,16.675 1.637,17.11 13.725,17.35 5.175,17.75 21.35,18.25 1.63,18.489 13.725,18.925 14.5,19.25 15.5,19.25 21.35,19.9 4.2,20.475 6.275,20.55 8.825,20.8 11.575,20.8 4.625,21.75 14.575,22.8 15.475,22.8 16.225,22.8 4.375,23.425 15.525,25.5 10.3,25.55 13.125,25.675 21.332,26.008 14.175,26.45 3.95,26.6 9.275,26.65 12.475,26.65 19.975,26.775 4.285,27.143 7.725,27.375 19.975,27.675 21.305,28.368 15,28.425 3.425,29.3 15.9,30.55 21.31,30.915 14.15,31.975 21.305,32.853 14.033,33.031 19.625,33.875 11.887,34.269 21.279,35.323 0.653,36.418 19.2,36.6 20.439,36.619 21.278,36.914 17.15,37.575 0.7,38.95 17.85,38.975 15.825,39.025 21.35,39.225 5.3,39.3 15.337,40.54 17.85,40.6 4.449,40.843 21.35,41.025 0.7,41.35 5.3,41.6 14.277,41.992 15.4,42 16.309,42.895 13.158,42.933 21.325,43 14.846,43.231 0.675,43.575 19.65,43.65 21.328,43.945 9.551,44.038 12.592,44.046 6.694,44.058 8.07,44.049 11.115,44.063 18.4,44.725 3.975,44.825 20.683,44.862 5.425,44.975 6.677,45.058 12.553,45.614 19.15,45.669 8.688,45.977 10.567,46.001 0.675,46.225 6.681,46.535 17.2,46.525 9.676,46.686 11.3,46.71 7.949,46.728 14.756,46.803 21.313,46.886 12.571,46.964 19.707,47.203 18.395,47.263 8.679,47.413 10.573,47.403 14.508,47.891 10.575,48.075 8.674,48.101 6.706,48.17 12.576,48.181 21.3,48.45 0.65,48.675 7.972,48.793 9.675,48.8 11.3,48.8 17.525,48.825 19.892,49.085 12.569,49.262 8.65,49.525 10.575,49.525 6.668,49.882 15.15,50 21.324,50.045 16.6,50.075 18.398,50.098 13.836,50.13 2.403,50.284 12.576,50.321 0.686,50.575 17.925,50.7 6.695,51.323 10.169,51.326 7.864,51.346 9.106,51.346 11.373,51.339 12.565,51.339 15.55,51.35 21.354,51.593 5.525,51.9 2.739,52.002 4.275,52.025 13.725,52.15 17.375,52.225 16.376,52.234 18.275,52.45 13.725,52.85 15.625,52.925 18.395,53.073 14.7,53.125 21.324,53.117 0.689,53.306 4.283,53.333 13.725,53.55 2.528,53.58 19.825,54 14.974,54.123 13.725,54.35 16.3,54.34 4.325,54.575 5.525,55.05 13.725,55.05 21.325,55.325 0.675,55.35 2.5,55.35 4.5,55.35 14.6,55.35 16.25,55.375 18.823,55.36
GNDDetect: CN3.11 R14.2 | length 4.2
  Top Layer w0.12: R14.2@2.125,10.675 R14.2@2.125,10.77 ; R14.2@2.138,10.783 2.113,10.783 1.93,10.965 1.93,10.98 1.619,11.29 1.619,12.536 2.368,13.285 CN3.11@3.393,13.285
I2C3_SCL: R5.2 U2.15 U10.2 U11.13 U12.6 | length 45.7
  Top Layer w0.12: U2.15@6.108,47.175 6.066,47.134 4.38,47.134 2.335,45.089 2.335,39.89 4.277,37.948 4.277,37.037 3.479,36.24 3.479,35.754 R5.2@3.475,35.75 4.005,35.75 4.179,35.576 4.179,35.27 4.552,34.896 5.748,34.896 6.145,35.294 v1(6.145,35.332) ; 7.325,23.55 7.225,23.65 v1(7.225,25.225) 7.985,25.985 12.81,25.985 13.825,27 U10.2@14.525,27 14.95,27 15.1,26.85 15.1,26.7 16.45,25.35 16.45,24.95 16.635,24.765 U12.6@17.275,24.765 ; 7.328,23.547 7.878,23.547 U11.13@7.9,23.525
  Bottom Layer w0.12: v1(6.145,35.332) 6.566,34.911 7.985,34.911 8.284,34.612 8.284,34.238 6.532,32.486 6.532,25.918 v1(7.225,25.225)
I2C3_SDA: R4.2 U2.14 U10.1 U11.14 U12.5 | length 47.1
  Top Layer w0.12: R4.2@2.5,35.75 2.464,35.714 2.018,35.714 1.843,35.539 1.843,34.562 2.043,34.362 4.189,34.362 5.291,33.26 v1(6.225,33.26) ; R4.2@2.5,35.75 2.501,36.243 2.978,36.72 3.508,36.72 3.97,37.183 3.97,37.916 2.095,39.791 2.095,45.295 4.5,47.7 U2.14@6.108,47.7 ; U11.14@7.9,23.025 7.1,23.025 6.6,23.525 6.6,25.5 7.325,26.225 12.675,26.225 13.85,27.4 14.025,27.4 14.335,27.71 U10.1@14.35,27.725 ; U10.1@14.715,27.71 15.35,27.075 15.35,26.825 16.3,25.875 16.425,25.875 16.945,25.355 16.995,25.355 U12.5@17.05,25.3
  Bottom Layer w0.12: v1(6.225,33.26) 6.225,32.518 6.292,32.451 6.292,25.658 6.6,25.35 v1(6.6,24.825)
